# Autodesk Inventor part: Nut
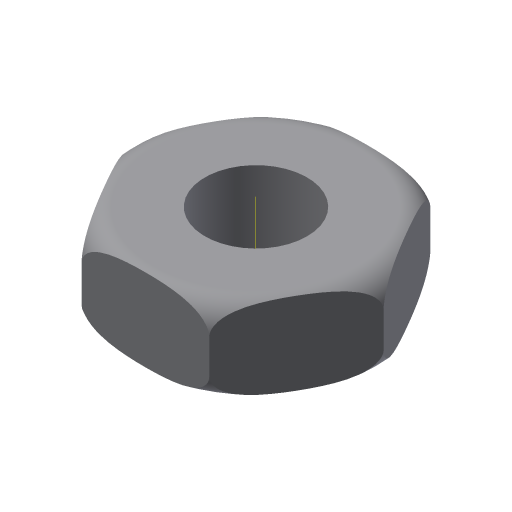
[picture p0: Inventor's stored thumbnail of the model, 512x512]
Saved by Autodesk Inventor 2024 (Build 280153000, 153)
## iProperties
Created: 2009-04
Part Number: Nut
Document SubType Name: Modeling
Designer: Sham
Density: 1 g/cm^3
Material: Generic
Appearance: Default
Mass: 4.65064 g
Surface Area: 21.3319 cm^2
Volume: 4.65064 cm^3
Author: Sham
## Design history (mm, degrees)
sketch "Sketch1"
  geometry: L1 (7.5, 12.99)-(15, 0); L2 (15, 0)-(7.5, -12.99); L3 (7.5, -12.99)-(-7.5, -12.99); L4 (-7.5, -12.99)-(-15, 0); L5 (-15, 0)-(-7.5, 12.99); L6 (-7.5, 12.99)-(7.5, 12.99); C1 r 6 at (0, 0); 1 further point
  constraints: 12 end point, 1 centre point, 1 coincident, 13 other
  dimensions: "d0" = 30 distance of L1.end L4.end; "d1" = 12 diameter of C1
extrude "Extrusion1" new body sketch "Sketch1" distance "d2" = 12; taper "d3" = 0 deg
sketch "Sketch2"
  geometry: L1 (-12, 0)-(-12, -0.022); L2 (-15, 7)-(-15, 3); L3 (0, -2.87)-(0, 12.87) reference; A1 r 3 centre (-12, 7) between (-12, 10) and (-15, 7); A2 r 3 centre (-12, 3) between (-15, 3) and (-12, 0)
  constraints: 4 end point, 4 point on circle, 2 centre point, 1 tangent
revolve "Revolution1" sketch "Sketch2" stored, may be unused: angle "d7" = 90 deg
body "Solid1"
other parameters: "d6" = 90 deg
